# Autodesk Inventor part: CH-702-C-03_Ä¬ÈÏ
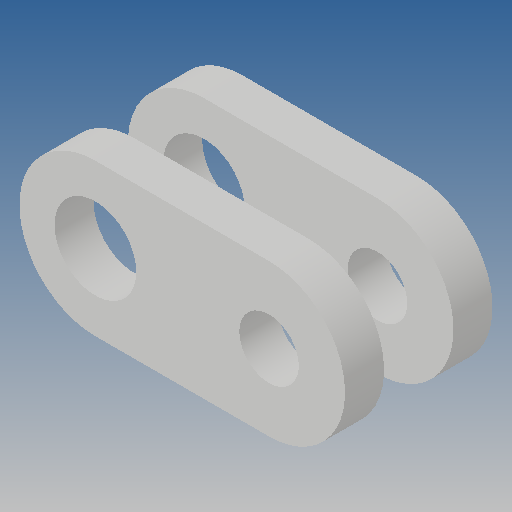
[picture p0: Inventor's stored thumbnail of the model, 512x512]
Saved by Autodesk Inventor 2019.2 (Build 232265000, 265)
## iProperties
Created: 2010-06
Part Number: CH-702-C-03_Ä¬ÈÏ
Material: Ogólny
Document SubType Name: Modeling
Designer: CADENGINEERING4
Density: 1 g/cm^3
Appearance: Domyślna
Author: CADENGINEERING4
Revision Number: ÈÎºÎ
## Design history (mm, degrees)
feature "NONE"
feature "NONE:1"
node "Bryła1"
node "Bryła2"
